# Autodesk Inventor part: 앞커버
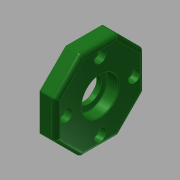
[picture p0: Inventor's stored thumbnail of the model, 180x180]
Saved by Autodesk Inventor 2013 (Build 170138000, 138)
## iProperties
Created: 2015-11
Part Number: 앞커버
Material: 알루미늄 6061
Document SubType Name: Modeling
Designer: mduedu
Density: 1 g/cm^3
Author: mduedu
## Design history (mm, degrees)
sketch "스케치5" dims "d66" = 60
  geometry: L1 (12.426, 30)-(30, 12.426); L2 (30, 12.426)-(30, -12.426); L3 (30, -12.426)-(12.426, -30); L4 (12.426, -30)-(-12.426, -30); L5 (-12.426, -30)-(-30, -12.426); L6 (-30, -12.426)-(-30, 12.426); L7 (-30, 12.426)-(-12.426, 30); L8 (-12.426, 30)-(12.426, 30); 4 further points
  constraints: 16 end point, 2 coincident, 2 vertical alignment, 1 midpoint, 19 other
extrude "돌출2" new body sketch "스케치5" distance "d67" = 11; taper "d68" = 0 deg
sketch "스케치6"
  geometry: C1 r 16 at (0, 0); 1 further point
  constraints: 1 centre point, 1 coincident
  dimensions: "d69" = 32 diameter of C1
extrude "돌출3" join sketch "스케치6" distance "d70" = 3; taper "d71" = 0 deg
hole "구멍7" diameter "d98" = 25; stored, may be unused: countersink angle "d102" = 90 deg, drill point angle "d104" = 0 deg; dims "d96" = 10, "d97" = 10, "d99" = 6, "d100" = 4, "d101" = 2, "d103" = 3
hole "구멍8" diameter "d107" = 25; stored, may be unused: countersink angle "d111" = 90 deg, drill point angle "d113" = 0 deg; dims "d105" = 10, "d106" = 10, "d108" = 6, "d109" = 4, "d110" = 2, "d112" = 7.7
hole "구멍9" diameter "d116" = 17; stored, may be unused: countersink angle "d120" = 90 deg, drill point angle "d122" = 0 deg; dims "d114" = 10, "d115" = 10, "d117" = 6, "d118" = 4, "d119" = 2, "d121" = 7.7
chamfer "모따기2" distance "d123" = 0.6; stored, may be unused: second distance "d124" = 2, angle "d125" = 30 deg
fillet "모깎기11" dims "d126" = 0.3
fillet "모깎기12" dims "d127" = 1
fillet "모깎기13" dims "d128" = 3
fillet "모깎기14" dims "d129" = 3
fillet "모깎기15" dims "d130" = 0.3
sketch "스케치8" dims "d131" = 46
  geometry: 3 further points
  constraints: 2 vertical alignment, 1 coincident, 2 other
hole "구멍10" sketch "스케치8" at (0, 23) diameter "d132" = 4.5; stored, may be unused: countersink angle "d136" = 90 deg, drill point angle "d138" = 0 deg; dims "d133" = 6, "d134" = 8, "d135" = 4.6, "d137" = 7.7
node "솔리드2"
pattern_circular "원형 패턴4" dims angle "d140" = 360 deg
